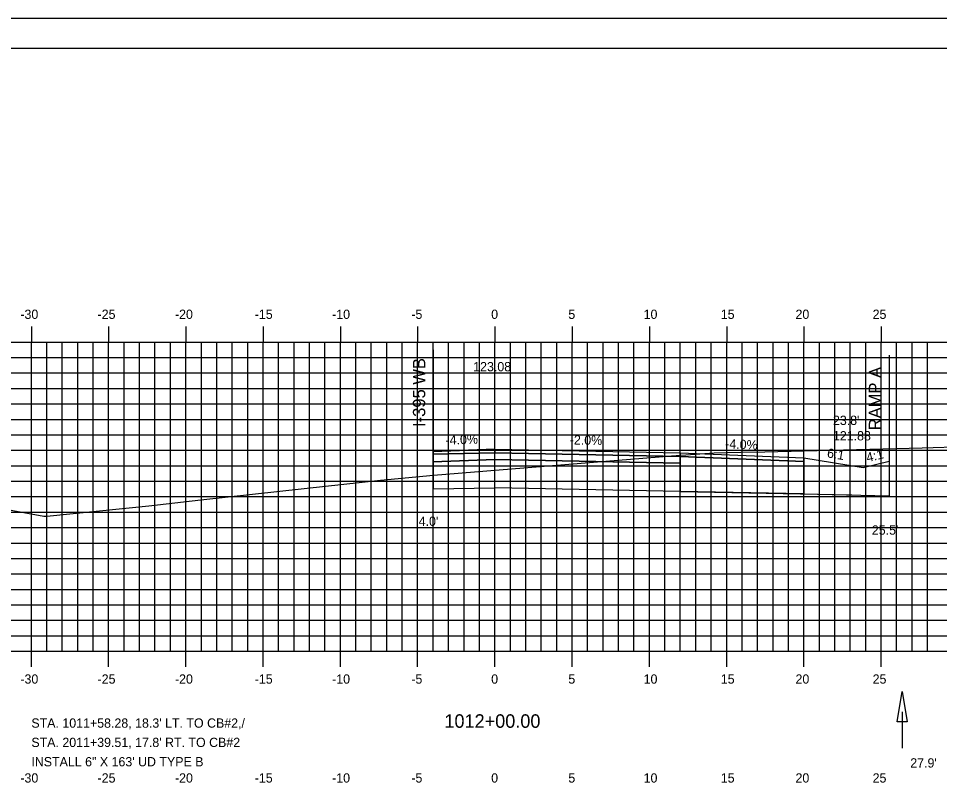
# Model space of a CAD drawing. Extents: x 852404 to 852575, y 365624 to 365734.
# Drawn here: x 852456 to 852515.6, y 365684.3 to 365734 of the extents above; entities that cross this region are included whole.
import ezdxf

# ---------------------------------------------------------------- set-up
doc = ezdxf.new("R2010")
doc.units = 0
for name, color, linetype in [('ANNOTATION', 7, 'Continuous'), ('BORDER', 7, 'Continuous'), ('D_Drainage_Ditch_Line', 7, 'Continuous'), ('D_Roadway_Centerline', 7, 'Continuous'), ('D_Roadway_Centerline_Text', 7, 'Continuous'), ('D_Roadway_Edge_Shoulder', 7, 'Continuous'), ('D_Roadway_Edge_TW', 7, 'Continuous'), ('D_Roadway_FinishedGrade', 7, 'Continuous'), ('D_Roadway_Pavement', 7, 'Continuous'), ('D_Roadway_SubGrade', 7, 'Continuous'), ('D_Text_Standard', 7, 'Continuous'), ('Default', 7, 'Continuous'), ('H_V ANNOTATION', 7, 'Continuous'), ('MAJOR', 7, 'Continuous'), ('MINOR', 7, 'Continuous'), ('PLOT BOUNDARY', 7, 'Continuous'), ('S_Roadway_Centerline', 7, 'Continuous')]:
    doc.layers.add(name, color=color, linetype=linetype)

msp = doc.modelspace()

# ---------------------------------------------------------------- linework, layer by layer
at = {"layer": 'BORDER'}
msp.add_lwpolyline([(852411.792, 365627.027), (852571.792, 365627.027), (852571.792, 365732.027), (852411.792, 365732.027)], close=True, dxfattribs=at)
at = {"layer": 'D_Drainage_Ditch_Line'}
msp.add_line((852513.152, 365689.11), (852513.152, 365686.76), dxfattribs=at)
msp.add_lwpolyline([(852513.48, 365688.454), (852512.824, 365688.454), (852513.152, 365690.422)], close=True, dxfattribs=at)
at = {"layer": 'D_Roadway_Centerline'}
for p, q in [((852498.792, 365703.365), (852509.882, 365703.143)), ((852506.791, 365703.205), (852512.298, 365703.076))]:
    msp.add_line(p, q, dxfattribs=at)
for points in [[(852482.791, 365705.945), (852482.791, 365705.945), (852486.79, 365706.105), (852486.792, 365706.105), (852498.788, 365705.865), (852498.792, 365705.865), (852506.79, 365705.545), (852506.791, 365705.545)], [(852506.791, 365705.545), (852510.63, 365704.905), (852512.298, 365705.322)]]:
    msp.add_lwpolyline(points, dxfattribs=at)
at = {"layer": 'D_Roadway_Edge_Shoulder'}
for points in [[(852486.792, 365706.105), (852482.791, 365705.945), (852482.791, 365705.779), (852486.792, 365705.855)], [(852498.792, 365705.865), (852506.791, 365705.545), (852506.79, 365705.295), (852498.792, 365705.615)]]:
    msp.add_lwpolyline(points, close=True, dxfattribs=at)
at = {"layer": 'D_Roadway_Edge_TW'}
msp.add_lwpolyline([(852486.792, 365706.105), (852498.792, 365705.865), (852498.792, 365705.615), (852486.792, 365705.855)], close=True, dxfattribs=at)
msp.add_lwpolyline([(852498.792, 365705.865), (852498.792, 365705.699)], dxfattribs=at)
at = {"layer": 'D_Roadway_FinishedGrade'}
for p, q in [((852486.792, 365706.105), (852486.792, 365705.855)), ((852486.792, 365706.105), (852486.792, 365705.855)), ((852482.791, 365705.945), (852482.791, 365705.695)), ((852498.792, 365705.865), (852498.792, 365705.615)), ((852506.79, 365705.545), (852506.79, 365705.295))]:
    msp.add_line(p, q, dxfattribs=at)
at = {"layer": 'D_Roadway_Pavement'}
for points in [[(852486.792, 365705.855), (852482.791, 365705.779), (852482.791, 365705.279), (852486.792, 365705.439)], [(852486.792, 365705.855), (852498.792, 365705.615), (852498.792, 365705.199), (852486.792, 365705.439)]]:
    msp.add_lwpolyline(points, close=True, dxfattribs=at)
msp.add_lwpolyline([(852498.792, 365705.699), (852498.792, 365705.199)], dxfattribs=at)
msp.add_lwpolyline([(852498.792, 365705.699), (852498.792, 365705.199)], dxfattribs=at)
at = {"layer": 'D_Roadway_SubGrade'}
for p, q in [((852482.791, 365712.526), (852482.791, 365703.525)), ((852512.297, 365712.186), (852512.297, 365703.076))]:
    msp.add_line(p, q, dxfattribs=at)
for points in [[(852486.792, 365705.439), (852482.791, 365705.279), (852482.791, 365705.779), (852482.791, 365705.945), (852482.791, 365703.525), (852486.792, 365703.605)], [(852486.792, 365705.439), (852498.792, 365705.199), (852498.792, 365703.365), (852486.792, 365703.605)], [(852498.792, 365705.199), (852498.792, 365705.615), (852506.79, 365705.295), (852506.791, 365705.545), (852506.791, 365703.205), (852498.792, 365703.365)]]:
    msp.add_lwpolyline(points, close=True, dxfattribs=at)
msp.add_lwpolyline([(852498.792, 365705.199), (852498.792, 365703.365)], dxfattribs=at)
at = {"layer": 'Default'}
msp.add_line((852506.791, 365705.545), (852510.63, 365704.905), dxfattribs=at)
at = {"layer": 'MAJOR'}
for p, q in [((852456.792, 365714.029), (852456.792, 365713.027)), ((852461.792, 365714.029), (852461.792, 365713.027)), ((852466.792, 365714.029), (852466.792, 365713.027)), ((852471.792, 365714.029), (852471.792, 365713.027)), ((852476.792, 365714.029), (852476.792, 365713.027)), ((852481.792, 365714.029), (852481.792, 365713.027)), ((852486.792, 365714.029), (852486.792, 365713.027)), ((852491.792, 365714.029), (852491.792, 365713.027)), ((852496.792, 365714.029), (852496.792, 365713.027)), ((852501.792, 365714.029), (852501.792, 365713.027)), ((852506.792, 365714.029), (852506.792, 365713.027)), ((852511.792, 365714.029), (852511.792, 365713.027)), ((852416.792, 365713.027), (852556.792, 365713.027)), ((852416.792, 365713.027), (852556.792, 365713.027)), ((852456.792, 365693.027), (852456.792, 365713.027)), ((852461.792, 365693.027), (852461.792, 365713.027)), ((852466.792, 365693.027), (852466.792, 365713.027)), ((852471.792, 365693.027), (852471.792, 365713.027)), ((852476.792, 365693.027), (852476.792, 365713.027)), ((852481.792, 365693.027), (852481.792, 365713.027)), ((852486.792, 365693.027), (852486.792, 365713.027)), ((852491.792, 365693.027), (852491.792, 365713.027)), ((852496.792, 365693.027), (852496.792, 365713.027)), ((852501.792, 365693.027), (852501.792, 365713.027)), ((852506.792, 365693.027), (852506.792, 365713.027)), ((852511.792, 365693.027), (852511.792, 365713.027)), ((852416.792, 365708.027), (852556.792, 365708.027)), ((852416.792, 365703.027), (852556.792, 365703.027)), ((852416.792, 365698.027), (852556.792, 365698.027)), ((852416.792, 365693.027), (852556.792, 365693.027)), ((852416.792, 365693.027), (852556.792, 365693.027)), ((852456.792, 365692.025), (852456.792, 365693.027)), ((852461.792, 365692.025), (852461.792, 365693.027)), ((852466.792, 365692.025), (852466.792, 365693.027)), ((852471.792, 365692.025), (852471.792, 365693.027)), ((852476.792, 365692.025), (852476.792, 365693.027)), ((852481.792, 365692.025), (852481.792, 365693.027)), ((852486.792, 365692.025), (852486.792, 365693.027)), ((852491.792, 365692.025), (852491.792, 365693.027)), ((852496.792, 365692.025), (852496.792, 365693.027)), ((852501.792, 365692.025), (852501.792, 365693.027)), ((852506.792, 365692.025), (852506.792, 365693.027)), ((852511.792, 365692.025), (852511.792, 365693.027))]:
    msp.add_line(p, q, dxfattribs=at)
at = {"layer": 'MINOR'}
for p, q in [((852457.792, 365693.027), (852457.792, 365713.027)), ((852458.792, 365693.027), (852458.792, 365713.027)), ((852459.792, 365693.027), (852459.792, 365713.027)), ((852460.792, 365693.027), (852460.792, 365713.027)), ((852462.792, 365693.027), (852462.792, 365713.027)), ((852463.792, 365693.027), (852463.792, 365713.027)), ((852464.792, 365693.027), (852464.792, 365713.027)), ((852465.792, 365693.027), (852465.792, 365713.027)), ((852467.792, 365693.027), (852467.792, 365713.027)), ((852468.792, 365693.027), (852468.792, 365713.027)), ((852469.792, 365693.027), (852469.792, 365713.027)), ((852470.792, 365693.027), (852470.792, 365713.027)), ((852472.792, 365693.027), (852472.792, 365713.027)), ((852473.792, 365693.027), (852473.792, 365713.027)), ((852474.792, 365693.027), (852474.792, 365713.027)), ((852475.792, 365693.027), (852475.792, 365713.027)), ((852477.792, 365693.027), (852477.792, 365713.027)), ((852478.792, 365693.027), (852478.792, 365713.027)), ((852479.792, 365693.027), (852479.792, 365713.027)), ((852480.792, 365693.027), (852480.792, 365713.027)), ((852482.792, 365693.027), (852482.792, 365713.027)), ((852483.792, 365693.027), (852483.792, 365713.027)), ((852484.792, 365693.027), (852484.792, 365713.027)), ((852485.792, 365693.027), (852485.792, 365713.027)), ((852487.792, 365693.027), (852487.792, 365713.027)), ((852488.792, 365693.027), (852488.792, 365713.027)), ((852489.792, 365693.027), (852489.792, 365713.027)), ((852490.792, 365693.027), (852490.792, 365713.027)), ((852492.792, 365693.027), (852492.792, 365713.027)), ((852493.792, 365693.027), (852493.792, 365713.027)), ((852494.792, 365693.027), (852494.792, 365713.027)), ((852495.792, 365693.027), (852495.792, 365713.027)), ((852497.792, 365693.027), (852497.792, 365713.027)), ((852498.792, 365693.027), (852498.792, 365713.027)), ((852499.792, 365693.027), (852499.792, 365713.027)), ((852500.792, 365693.027), (852500.792, 365713.027)), ((852502.792, 365693.027), (852502.792, 365713.027)), ((852503.792, 365693.027), (852503.792, 365713.027)), ((852504.792, 365693.027), (852504.792, 365713.027)), ((852505.792, 365693.027), (852505.792, 365713.027)), ((852507.792, 365693.027), (852507.792, 365713.027)), ((852508.792, 365693.027), (852508.792, 365713.027)), ((852509.792, 365693.027), (852509.792, 365713.027)), ((852510.792, 365693.027), (852510.792, 365713.027)), ((852512.792, 365693.027), (852512.792, 365713.027)), ((852513.792, 365693.027), (852513.792, 365713.027)), ((852514.792, 365693.027), (852514.792, 365713.027)), ((852416.792, 365712.027), (852556.792, 365712.027)), ((852416.792, 365711.027), (852556.792, 365711.027)), ((852416.792, 365710.027), (852556.792, 365710.027)), ((852416.792, 365709.027), (852556.792, 365709.027)), ((852416.792, 365707.027), (852556.792, 365707.027)), ((852416.792, 365706.027), (852556.792, 365706.027)), ((852416.792, 365705.027), (852556.792, 365705.027)), ((852416.792, 365704.027), (852556.792, 365704.027)), ((852416.792, 365702.027), (852556.792, 365702.027)), ((852416.792, 365701.027), (852556.792, 365701.027)), ((852416.792, 365700.027), (852556.792, 365700.027)), ((852416.792, 365699.027), (852556.792, 365699.027)), ((852416.792, 365697.027), (852556.792, 365697.027)), ((852416.792, 365696.027), (852556.792, 365696.027)), ((852416.792, 365695.027), (852556.792, 365695.027)), ((852416.792, 365694.027), (852556.792, 365694.027))]:
    msp.add_line(p, q, dxfattribs=at)
at = {"layer": 'PLOT BOUNDARY'}
msp.add_lwpolyline([(852403.699, 365623.968), (852573.699, 365623.968), (852573.699, 365733.968), (852403.699, 365733.968)], close=True, dxfattribs=at)
at = {"layer": 'S_Roadway_Centerline'}
msp.add_lwpolyline([(852416.792, 365706.364), (852418.009, 365706.332), (852424.673, 365706.138), (852432.08, 365705.942), (852432.36, 365705.933), (852432.934, 365705.868), (852444.494, 365704.135), (852445.247, 365704.022), (852445.536, 365703.974), (852457.608, 365701.769), (852457.783, 365701.761), (852464.401, 365702.438), (852467.757, 365702.817), (852474.44, 365703.544), (852479.393, 365704.094), (852482.824, 365704.407), (852498.227, 365705.672), (852500.98, 365705.857), (852502.705, 365705.908), (852504.265, 365705.936), (852514.448, 365706.178), (852517.274, 365706.274)], dxfattribs=at)

# ---------------------------------------------------------------- texts
at = {"layer": 'ANNOTATION'}
for s, height, rotation, p in [('I-395 WB', 0.8, 90, (852482.284, 365707.536)), ('RAMP A', 0.8, 90, (852511.79, 365707.318)), ('-4.0%', 0.6, 2.2904, (852483.607, 365706.378)), ('-2.0%', 0.6, 358.85422, (852491.633, 365706.408)), ('-4.0%', 0.6, 357.7093, (852501.687, 365706.15)), ('6:1', 0.6, 350.53768, (852508.256, 365705.571)), ('4:1', 0.6, 14.02595, (852510.909, 365705.25))]:
    msp.add_text(s, height=height, rotation=rotation, dxfattribs=at).set_placement(p)
at = {"layer": 'D_Roadway_Centerline'}
for s, p in [('C', (852486.786, 365706.105)), ('L', (852486.792, 365706.097))]:
    msp.add_text(s, height=0.0146, dxfattribs=at).set_placement(p)
at = {"layer": 'D_Roadway_Centerline_Text'}
msp.add_text('123.08', height=0.6, dxfattribs=at).set_placement((852485.387, 365711.137))
at = {"layer": 'D_Text_Standard'}
for s, p in [("23.8' ", (852508.67, 365707.666)), ('121.88', (852508.67, 365706.666)), ("4.0'", (852481.858, 365701.136)), ("25.5'", (852511.187, 365700.565)), ("STA. 1011+58.28, 18.3' LT. TO CB#2,/", (852456.792, 365688.077)), ("STA. 2011+39.51, 17.8' RT. TO CB#2", (852456.792, 365686.827)), ('INSTALL 6" X 163\' UD TYPE B', (852456.792, 365685.577)), ("27.9'", (852513.674, 365685.5))]:
    msp.add_text(s, height=0.6, dxfattribs=at).set_placement(p)
at = {"layer": 'H_V ANNOTATION'}
for s, height, p in [('-30', 0.6, (852456.08, 365714.527)), ('-25', 0.6, (852461.077, 365714.527)), ('-20', 0.6, (852466.085, 365714.527)), ('-15', 0.6, (852471.249, 365714.527)), ('-10', 0.6, (852476.257, 365714.527)), ('-5', 0.6, (852481.382, 365714.527)), ('0', 0.6, (852486.551, 365714.527)), ('5', 0.6, (852491.543, 365714.527)), ('10', 0.6, (852496.417, 365714.527)), ('15', 0.6, (852501.409, 365714.527)), ('20', 0.6, (852506.246, 365714.527)), ('25', 0.6, (852511.238, 365714.527)), ('-30', 0.6, (852456.08, 365690.927)), ('-25', 0.6, (852461.077, 365690.927)), ('-20', 0.6, (852466.085, 365690.927)), ('-15', 0.6, (852471.249, 365690.927)), ('-10', 0.6, (852476.257, 365690.927)), ('-5', 0.6, (852481.382, 365690.927)), ('0', 0.6, (852486.551, 365690.927)), ('5', 0.6, (852491.543, 365690.927)), ('10', 0.6, (852496.417, 365690.927)), ('15', 0.6, (852501.409, 365690.927)), ('20', 0.6, (852506.246, 365690.927)), ('25', 0.6, (852511.238, 365690.927)), ('1012+00.00', 0.875, (852483.523, 365688.07)), ('-30', 0.6, (852456.08, 365684.527)), ('-25', 0.6, (852461.077, 365684.527)), ('-20', 0.6, (852466.085, 365684.527)), ('-15', 0.6, (852471.249, 365684.527)), ('-10', 0.6, (852476.257, 365684.527)), ('-5', 0.6, (852481.382, 365684.527)), ('0', 0.6, (852486.551, 365684.527)), ('5', 0.6, (852491.543, 365684.527)), ('10', 0.6, (852496.417, 365684.527)), ('15', 0.6, (852501.409, 365684.527)), ('20', 0.6, (852506.246, 365684.527)), ('25', 0.6, (852511.238, 365684.527))]:
    msp.add_text(s, height=height, dxfattribs=at).set_placement(p)

doc.saveas('drawing.dxf')
